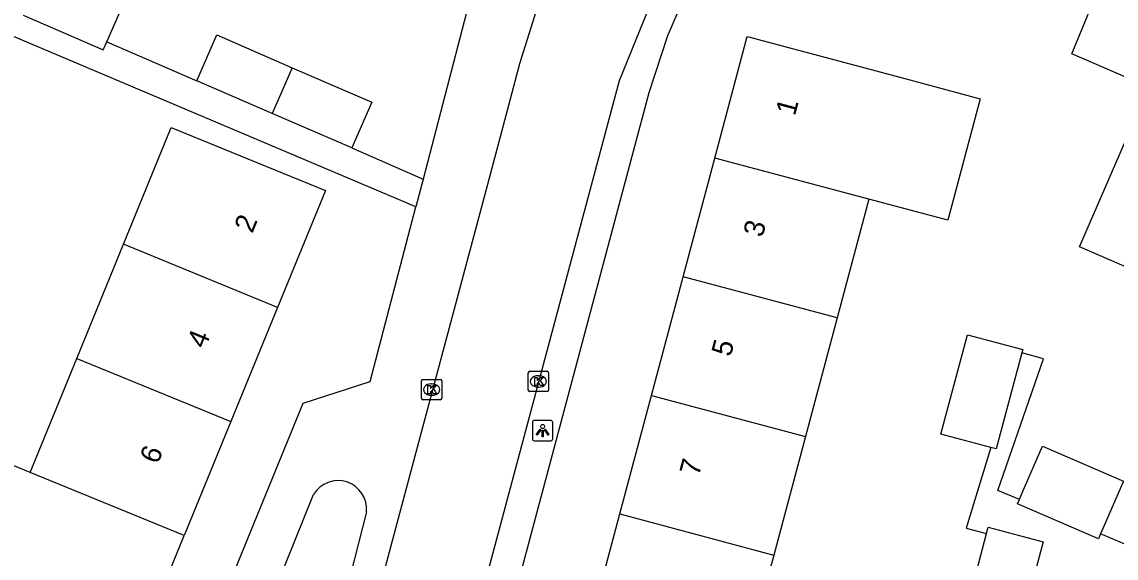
# Model space of a CAD drawing. Extents: x 162812 to 163818, y 381639 to 382470.
# Drawn here: x 163318.4 to 163372.2, y 381923.4 to 381949.7 of the extents above; entities that cross this region are included whole.
import ezdxf

# ---------------------------------------------------------------- set-up
doc = ezdxf.new("R2010")
doc.units = 0
for name, color, linetype in [('IMGEO_Kolk', 7, 'Continuous'), ('IMGEO_Lichtpunt', 7, 'Continuous'), ('IMGEO_Pand', 7, 'Continuous'), ('IMGEO_Pand_nummerreeks', 7, 'Continuous'), ('IMGEO_Rijbaan_lokaal_open', 7, 'Continuous'), ('IMGEO_Voetpad_open', 7, 'Continuous')]:
    doc.layers.add(name, color=color, linetype=linetype)

msp = doc.modelspace()

# ---------------------------------------------------------------- linework, layer by layer
at = {"layer": 'IMGEO_Kolk'}
for p, q in [((163343.293, 381931.63), (163343.293, 381932.482)), ((163343.368, 381932.556), (163344.22, 381932.556)), ((163344.294, 381932.482), (163344.294, 381931.63)), ((163338.037, 381931.227), (163338.037, 381932.079)), ((163338.112, 381932.153), (163338.964, 381932.153)), ((163339.038, 381932.079), (163339.038, 381931.227)), ((163343.781, 381932.336), (163343.806, 381932.336)), ((163338.525, 381931.933), (163338.55, 381931.933)), ((163344.22, 381931.556), (163343.368, 381931.556)), ((163343.804, 381931.776), (163343.779, 381931.776)), ((163338.964, 381931.153), (163338.112, 381931.153)), ((163338.548, 381931.373), (163338.523, 381931.373))]:
    msp.add_line(p, q, dxfattribs=at)
for points in [[(163343.293, 381931.63), (163343.293, 381932.482)], [(163343.368, 381932.556), (163344.22, 381932.556)], [(163344.294, 381932.482), (163344.294, 381931.63)], [(163338.037, 381931.227), (163338.037, 381932.079)], [(163338.112, 381932.153), (163338.964, 381932.153)], [(163339.038, 381932.079), (163339.038, 381931.227)], [(163343.614, 381932.256), (163343.737, 381932.256), (163343.737, 381932.105), (163343.867, 381932.256), (163344.031, 381932.256), (163343.885, 381932.105), (163344.038, 381931.856), (163343.886, 381931.856), (163343.801, 381932.02), (163343.737, 381931.953), (163343.737, 381931.856), (163343.614, 381931.856), (163343.614, 381932.256)], [(163338.358, 381931.853), (163338.481, 381931.853), (163338.481, 381931.702), (163338.611, 381931.853), (163338.775, 381931.853), (163338.629, 381931.702), (163338.782, 381931.453), (163338.63, 381931.453), (163338.545, 381931.617), (163338.481, 381931.55), (163338.481, 381931.453), (163338.358, 381931.453), (163338.358, 381931.853)], [(163344.22, 381931.556), (163343.368, 381931.556)], [(163338.964, 381931.153), (163338.112, 381931.153)]]:
    msp.add_lwpolyline(points, dxfattribs=at)
for centre, start, end in [((163343.37, 381932.48), 91.552, 178.448), ((163343.37, 381932.48), 91.552, 178.448), ((163344.218, 381932.48), 1.552, 88.448), ((163344.218, 381932.48), 1.552, 88.448), ((163338.114, 381932.077), 91.552, 178.448), ((163338.114, 381932.077), 91.552, 178.448), ((163338.962, 381932.077), 1.552, 88.448), ((163338.962, 381932.077), 1.552, 88.448), ((163343.37, 381931.632), 181.552, 268.448), ((163343.37, 381931.632), 181.552, 268.448), ((163344.218, 381931.632), 271.552, 358.448), ((163344.218, 381931.632), 271.552, 358.448), ((163338.114, 381931.229), 181.552, 268.448), ((163338.114, 381931.229), 181.552, 268.448), ((163338.962, 381931.229), 271.552, 358.448), ((163338.962, 381931.229), 271.552, 358.448)]:
    msp.add_arc(centre, 0.0765, start, end, dxfattribs=at)
for centre, major_axis, ratio, start_param, end_param in [((163343.78, 381932.056), (-0.387, 0.002), 0.722429, 4.712389, 7.853982), ((163343.805, 381932.056), (-0.39, 0.002), 0.717154, 1.570796, 4.712389), ((163338.524, 381931.653), (-0.387, 0.002), 0.722429, 4.712389, 7.853982), ((163338.549, 381931.653), (-0.39, 0.002), 0.717154, 1.570796, 4.712389)]:
    msp.add_ellipse(centre, major_axis=major_axis, ratio=ratio, start_param=start_param, end_param=end_param, dxfattribs=at)
at = {"layer": 'IMGEO_Lichtpunt'}
for p, q in [((163343.5, 381930.039), (163343.5, 381929.232)), ((163343.5, 381930.039), (163343.5, 381929.232)), ((163344.402, 381930.134), (163343.594, 381930.134)), ((163344.402, 381930.134), (163343.594, 381930.134)), ((163344.496, 381929.232), (163344.496, 381930.039)), ((163344.496, 381929.232), (163344.496, 381930.039)), ((163343.594, 381929.138), (163344.402, 381929.138)), ((163343.594, 381929.138), (163344.402, 381929.138))]:
    msp.add_line(p, q, dxfattribs=at)
for points in [[(163343.874, 381929.703), (163343.913, 381929.675), (163343.725, 381929.413), (163343.687, 381929.44), (163343.874, 381929.703)], [(163343.976, 381929.655), (163344.023, 381929.655), (163344.023, 381929.333), (163343.976, 381929.333), (163343.976, 381929.655)], [(163344.086, 381929.675), (163344.124, 381929.702), (163344.311, 381929.44), (163344.272, 381929.412), (163344.086, 381929.675)]]:
    msp.add_lwpolyline(points, dxfattribs=at)
msp.add_circle((163343.999, 381929.837), 0.0994, dxfattribs=at)
for centre, start, end in [((163343.594, 381930.039), 90, 180), ((163343.594, 381930.039), 90, 180), ((163344.402, 381930.039), 0, 90), ((163344.402, 381930.039), 0, 90), ((163343.594, 381929.232), 180, 270), ((163343.594, 381929.232), 180, 270), ((163344.402, 381929.232), 270, 0), ((163344.402, 381929.232), 270, 360)]:
    msp.add_arc(centre, 0.0946, start, end, dxfattribs=at)
at = {"layer": 'IMGEO_Pand'}
for points in [[(163322.558, 381948.77), (163323.491, 381950.918), (163319.554, 381952.63)], [(163373.829, 381946.533), (163370.045, 381948.172), (163370.933, 381950.319)], [(163318.443, 381950.075), (163322.381, 381948.363), (163322.558, 381948.77)], [(163326.983, 381946.848), (163327.959, 381949.099), (163331.672, 381947.49)], [(163352.476, 381943.044), (163354.072, 381949.025), (163361.645, 381947.004), (163365.541, 381945.965), (163363.945, 381939.984), (163360.049, 381941.022)], [(163331.672, 381947.49), (163330.693, 381945.24)], [(163331.672, 381947.49), (163335.591, 381945.791), (163334.615, 381943.54)], [(163330.693, 381945.24), (163326.983, 381946.848)], [(163376.439, 381936.074), (163370.425, 381938.682), (163373.829, 381946.533)], [(163334.615, 381943.54), (163330.693, 381945.24)], [(163323.368, 381938.801), (163325.723, 381944.553), (163328.684, 381943.341), (163333.311, 381941.446), (163330.956, 381935.694)], [(163350.919, 381937.209), (163352.476, 381943.044)], [(163360.049, 381941.022), (163352.476, 381943.044)], [(163360.049, 381941.022), (163358.491, 381935.186)], [(163321.07, 381933.19), (163323.368, 381938.801)], [(163330.956, 381935.694), (163323.368, 381938.801)], [(163349.361, 381931.371), (163350.919, 381937.209)], [(163358.491, 381935.186), (163350.919, 381937.209)], [(163330.956, 381935.694), (163328.658, 381930.083)], [(163358.491, 381935.186), (163356.934, 381929.351)], [(163366.062, 381928.804), (163363.607, 381929.459), (163364.913, 381934.355), (163367.631, 381933.63), (163367.588, 381933.47)], [(163318.773, 381927.579), (163321.07, 381933.19)], [(163321.07, 381933.19), (163328.658, 381930.083)], [(163367.588, 381933.47), (163366.324, 381928.734), (163366.062, 381928.804)], [(163347.804, 381925.536), (163349.361, 381931.371)], [(163349.361, 381931.371), (163356.934, 381929.351)], [(163328.658, 381930.083), (163326.361, 381924.472)], [(163356.934, 381929.351), (163355.377, 381923.515)], [(163367.464, 381926.247), (163367.606, 381926.577), (163368.596, 381928.872), (163372.581, 381927.153), (163371.589, 381924.859), (163371.457, 381924.553)], [(163318.773, 381927.579), (163316.169, 381928.645), (163313.815, 381922.896), (163316.419, 381921.83), (163319.38, 381920.618), (163324.007, 381918.723), (163326.361, 381924.472)], [(163326.361, 381924.472), (163318.773, 381927.579)], [(163371.457, 381924.553), (163371.353, 381924.312), (163367.372, 381926.034), (163367.464, 381926.247)], [(163346.247, 381919.701), (163347.804, 381925.536)], [(163347.804, 381925.536), (163355.377, 381923.515)], [(163367.306, 381919.896), (163364.795, 381920.557), (163365.853, 381924.577)], [(163365.853, 381924.577), (163365.933, 381924.881), (163368.632, 381924.17), (163367.494, 381919.847), (163367.306, 381919.896)], [(163355.377, 381923.515), (163353.825, 381917.699)]]:
    msp.add_lwpolyline(points, dxfattribs=at)
at = {"layer": 'IMGEO_Rijbaan_lokaal_open'}
for points in [[(163326.344, 381885.984), (163328.227, 381892.894), (163341.305, 381941.763), (163342.269, 381945.397), (163342.879, 381947.698), (163343.979, 381951.2), (163345.777, 381955.212), (163346.974, 381957.941)], [(163336.429, 381904.454), (163347.786, 381946.853), (163350.24, 381952.934), (163351.653, 381956.334)]]:
    msp.add_lwpolyline(points, dxfattribs=at)
at = {"layer": 'IMGEO_Voetpad_open'}
for points in [[(163352.498, 381954.506), (163350.15, 381949.06), (163349.232, 381946.25), (163337.135, 381901.001)], [(163337.762, 381940.645), (163309.811, 381952.487)], [(163340.821, 381951.498), (163340.262, 381950.209), (163338.117, 381942.001)], [(163322.558, 381948.77), (163326.983, 381946.848)], [(163334.615, 381943.54), (163338.117, 381942.001)], [(163338.117, 381942.001), (163337.762, 381940.645)], [(163325.4, 381914.344), (163332.221, 381930.991), (163335.518, 381932.057), (163337.762, 381940.645)], [(163367.464, 381926.247), (163366.403, 381926.697), (163368.646, 381933.17), (163367.588, 381933.47)], [(163366.062, 381928.804), (163364.841, 381924.838), (163365.853, 381924.577)], [(163335.33, 381925.646), (163331.019, 381908.748), (163326.319, 381910.623), (163332.732, 381926.487)], [(163373.622, 381923.634), (163371.457, 381924.553)]]:
    msp.add_lwpolyline(points, dxfattribs=at)
msp.add_arc((163333.938, 381925.779), 1.398, 354.5574, 149.568, dxfattribs=at)

# ---------------------------------------------------------------- texts
at = {"layer": 'IMGEO_Pand_nummerreeks'}
for s, rotation, p in [('1', 75.0586, (163356.416, 381945.087)), ('2', 67.7332, (163329.711, 381939.304)), ('3', 75.0586, (163354.819, 381939.105)), ('4', 67.7332, (163327.386, 381933.625)), ('5', 75.0586, (163353.252, 381933.233)), ('6', 67.7332, (163325.06, 381927.944)), ('7', 75.0586, (163351.685, 381927.361))]:
    msp.add_text(s, height=1, rotation=rotation, dxfattribs=at).set_placement(p)

doc.saveas('drawing.dxf')
